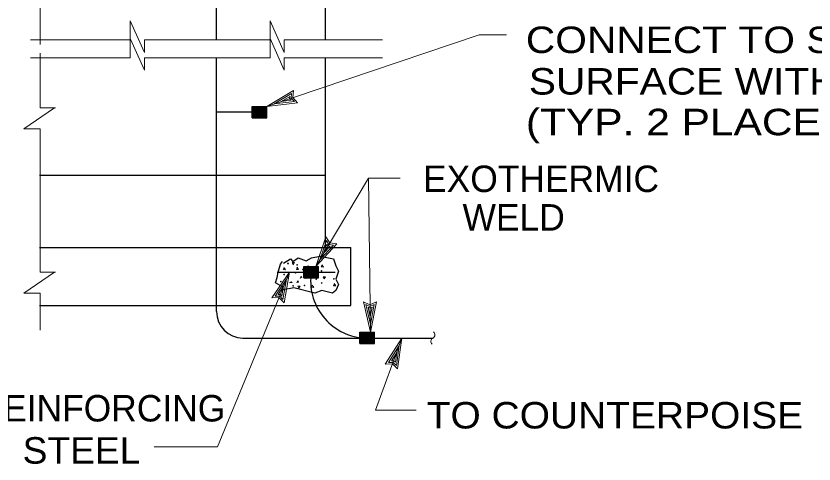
# Model space of a CAD drawing. Extents: x -39.6 to 16.1, y -17.6 to 34.
# Drawn here: x -5.055 to -1.286, y 5.207 to 7.321 of the extents above; entities that cross this region are included whole.
import ezdxf
from ezdxf.enums import TextEntityAlignment as Align

# ---------------------------------------------------------------- set-up
doc = ezdxf.new("R2010")
doc.units = 0
doc.header["$LTSCALE"] = 0.05
doc.layers.add('1', color=7, linetype='Continuous', lineweight=13)
doc.layers.add('2', color=7, linetype='Continuous', lineweight=13)

msp = doc.modelspace()

# ---------------------------------------------------------------- linework, layer by layer
at = {"layer": '1', "lineweight": 25}
for p, q in [((-4.10821, 7.20742), (-4.10821, 8.14042)), ((-3.59321, 7.20842), (-3.59321, 7.50542)), ((-4.10821, 5.92642), (-4.10821, 7.12442)), ((-3.59321, 6.22942), (-3.59321, 7.12442)), ((-4.10821, 6.86942), (-3.94021, 6.86942)), ((-3.94021, 6.84142), (-3.94021, 6.89442)), ((-3.94021, 6.89442), (-3.87121, 6.89442)), ((-3.94021, 6.89342), (-3.87121, 6.89342)), ((-3.94021, 6.89242), (-3.87121, 6.89242)), ((-3.94021, 6.89142), (-3.87121, 6.89142)), ((-3.94021, 6.89042), (-3.87121, 6.89042)), ((-3.94021, 6.88942), (-3.87121, 6.88942)), ((-3.94021, 6.88842), (-3.87121, 6.88842)), ((-3.94021, 6.88742), (-3.87121, 6.88742)), ((-3.94021, 6.88642), (-3.87121, 6.88642)), ((-3.94021, 6.88542), (-3.87121, 6.88542)), ((-3.94021, 6.88442), (-3.87121, 6.88442)), ((-3.94021, 6.88342), (-3.87121, 6.88342)), ((-3.94021, 6.88242), (-3.87121, 6.88242)), ((-3.94021, 6.88142), (-3.87121, 6.88142)), ((-3.94021, 6.88042), (-3.87121, 6.88042)), ((-3.94021, 6.87942), (-3.87121, 6.87942)), ((-3.94021, 6.87842), (-3.87121, 6.87842)), ((-3.94021, 6.87742), (-3.87121, 6.87742)), ((-3.94021, 6.87642), (-3.87121, 6.87642)), ((-3.94021, 6.87542), (-3.87121, 6.87542)), ((-3.94021, 6.87442), (-3.87121, 6.87442)), ((-3.94021, 6.87342), (-3.87121, 6.87342)), ((-3.94021, 6.87242), (-3.87121, 6.87242)), ((-3.94021, 6.87142), (-3.87121, 6.87142)), ((-3.94021, 6.87042), (-3.87121, 6.87042)), ((-3.94021, 6.86942), (-3.87121, 6.86942)), ((-3.94021, 6.86842), (-3.87121, 6.86842)), ((-3.94021, 6.86742), (-3.87121, 6.86742)), ((-3.94021, 6.86642), (-3.87121, 6.86642)), ((-3.94021, 6.86542), (-3.87121, 6.86542)), ((-3.94021, 6.86442), (-3.87121, 6.86442)), ((-3.94021, 6.86342), (-3.87121, 6.86342)), ((-3.94021, 6.86242), (-3.87121, 6.86242)), ((-3.94021, 6.86142), (-3.87121, 6.86142)), ((-3.94021, 6.86042), (-3.87121, 6.86042)), ((-3.87121, 6.84142), (-3.87121, 6.89442)), ((-3.94021, 6.85942), (-3.87121, 6.85942)), ((-3.94021, 6.85842), (-3.87121, 6.85842)), ((-3.94021, 6.85742), (-3.87121, 6.85742)), ((-3.94021, 6.85642), (-3.87121, 6.85642)), ((-3.94021, 6.85542), (-3.87121, 6.85542)), ((-3.94021, 6.85442), (-3.87121, 6.85442)), ((-3.94021, 6.85342), (-3.87121, 6.85342)), ((-3.94021, 6.85242), (-3.87121, 6.85242)), ((-3.94021, 6.85142), (-3.87121, 6.85142)), ((-3.94021, 6.85042), (-3.87121, 6.85042)), ((-3.94021, 6.84942), (-3.87121, 6.84942)), ((-3.94021, 6.84842), (-3.87121, 6.84842)), ((-3.94021, 6.84742), (-3.87121, 6.84742)), ((-3.94021, 6.84642), (-3.87121, 6.84642)), ((-3.94021, 6.84542), (-3.87121, 6.84542)), ((-3.94021, 6.84442), (-3.87121, 6.84442)), ((-3.94021, 6.84342), (-3.87121, 6.84342)), ((-3.94021, 6.84242), (-3.87121, 6.84242)), ((-3.94021, 6.84142), (-3.87121, 6.84142)), ((-4.94421, 6.57042), (-3.59321, 6.57042)), ((-4.94421, 6.22942), (-3.47421, 6.22942)), ((-3.47421, 5.95542), (-3.47421, 6.22942)), ((-3.82121, 6.11242), (-3.54821, 6.11242)), ((-3.69521, 6.08542), (-3.69521, 6.13842)), ((-3.69521, 6.13842), (-3.62621, 6.13842)), ((-3.69521, 6.13742), (-3.62621, 6.13742)), ((-3.69521, 6.13642), (-3.62621, 6.13642)), ((-3.69521, 6.13542), (-3.62621, 6.13542)), ((-3.69521, 6.13442), (-3.62621, 6.13442)), ((-3.69521, 6.13342), (-3.62621, 6.13342)), ((-3.69521, 6.13242), (-3.62621, 6.13242)), ((-3.69521, 6.13142), (-3.62621, 6.13142)), ((-3.69521, 6.13042), (-3.62621, 6.13042)), ((-3.69521, 6.12942), (-3.62621, 6.12942)), ((-3.69521, 6.12842), (-3.62621, 6.12842)), ((-3.69521, 6.12742), (-3.62621, 6.12742)), ((-3.69521, 6.12642), (-3.62621, 6.12642)), ((-3.69521, 6.12542), (-3.62621, 6.12542)), ((-3.69521, 6.12442), (-3.62621, 6.12442)), ((-3.69521, 6.12342), (-3.62621, 6.12342)), ((-3.69521, 6.12242), (-3.62621, 6.12242)), ((-3.69521, 6.12142), (-3.62621, 6.12142)), ((-3.69521, 6.12042), (-3.62621, 6.12042)), ((-3.69521, 6.11942), (-3.62621, 6.11942)), ((-3.69521, 6.11842), (-3.62621, 6.11842)), ((-3.69521, 6.11742), (-3.62621, 6.11742)), ((-3.69521, 6.11642), (-3.62621, 6.11642)), ((-3.69521, 6.11542), (-3.62621, 6.11542)), ((-3.69521, 6.11442), (-3.62621, 6.11442)), ((-3.69521, 6.11342), (-3.62621, 6.11342)), ((-3.69521, 6.11242), (-3.62621, 6.11242)), ((-3.69521, 6.11142), (-3.62621, 6.11142)), ((-3.69521, 6.11042), (-3.62621, 6.11042)), ((-3.69521, 6.10942), (-3.62621, 6.10942)), ((-3.69521, 6.10842), (-3.62621, 6.10842)), ((-3.69521, 6.10742), (-3.62621, 6.10742)), ((-3.69521, 6.10642), (-3.62621, 6.10642)), ((-3.62621, 6.08542), (-3.62621, 6.13842)), ((-3.69521, 6.10542), (-3.62621, 6.10542)), ((-3.69521, 6.10442), (-3.62621, 6.10442)), ((-3.69521, 6.10342), (-3.62621, 6.10342)), ((-3.69521, 6.10242), (-3.62621, 6.10242)), ((-3.69521, 6.10142), (-3.62621, 6.10142)), ((-3.69521, 6.10042), (-3.62621, 6.10042)), ((-3.69521, 6.09942), (-3.62621, 6.09942)), ((-3.69521, 6.09842), (-3.62621, 6.09842)), ((-3.69521, 6.09742), (-3.62621, 6.09742)), ((-3.69521, 6.09642), (-3.62621, 6.09642)), ((-3.69521, 6.09542), (-3.62621, 6.09542)), ((-3.69521, 6.09442), (-3.62621, 6.09442)), ((-3.69521, 6.09342), (-3.62621, 6.09342)), ((-3.69521, 6.09242), (-3.62621, 6.09242)), ((-3.69521, 6.09142), (-3.62621, 6.09142)), ((-3.69521, 6.09042), (-3.62621, 6.09042)), ((-3.69521, 6.08942), (-3.62621, 6.08942)), ((-3.69521, 6.08842), (-3.62621, 6.08842)), ((-3.69521, 6.08742), (-3.62621, 6.08742)), ((-3.69521, 6.08642), (-3.62621, 6.08642)), ((-3.69521, 6.08542), (-3.62621, 6.08542)), ((-4.94421, 5.95542), (-3.47421, 5.95542)), ((-3.43121, 5.77542), (-3.43121, 5.82842)), ((-3.43121, 5.82842), (-3.36221, 5.82842)), ((-3.43121, 5.82742), (-3.36221, 5.82742)), ((-3.43121, 5.82642), (-3.36221, 5.82642)), ((-3.43121, 5.82542), (-3.36221, 5.82542)), ((-3.43121, 5.82442), (-3.36221, 5.82442)), ((-3.43121, 5.82342), (-3.36221, 5.82342)), ((-3.43121, 5.82242), (-3.36221, 5.82242)), ((-3.43121, 5.82142), (-3.36221, 5.82142)), ((-3.43121, 5.82042), (-3.36221, 5.82042)), ((-3.43121, 5.81942), (-3.36221, 5.81942)), ((-3.43121, 5.81842), (-3.36221, 5.81842)), ((-3.43121, 5.81742), (-3.36221, 5.81742)), ((-3.43121, 5.81642), (-3.36221, 5.81642)), ((-3.43121, 5.81542), (-3.36221, 5.81542)), ((-3.43121, 5.81442), (-3.36221, 5.81442)), ((-3.43121, 5.81342), (-3.36221, 5.81342)), ((-3.43121, 5.81242), (-3.36221, 5.81242)), ((-3.43121, 5.81142), (-3.36221, 5.81142)), ((-3.43121, 5.81042), (-3.36221, 5.81042)), ((-3.43121, 5.80942), (-3.36221, 5.80942)), ((-3.43121, 5.80842), (-3.36221, 5.80842)), ((-3.43121, 5.80742), (-3.36221, 5.80742)), ((-3.43121, 5.80642), (-3.36221, 5.80642)), ((-3.43121, 5.80542), (-3.36221, 5.80542)), ((-3.43121, 5.80442), (-3.36221, 5.80442)), ((-3.36221, 5.77542), (-3.36221, 5.82842)), ((-3.98321, 5.80142), (-3.08721, 5.80142)), ((-3.43121, 5.80342), (-3.36221, 5.80342)), ((-3.43121, 5.80242), (-3.36221, 5.80242)), ((-3.43121, 5.80142), (-3.36221, 5.80142)), ((-3.43121, 5.80042), (-3.36221, 5.80042)), ((-3.43121, 5.79942), (-3.36221, 5.79942)), ((-3.43121, 5.79842), (-3.36221, 5.79842)), ((-3.43121, 5.79742), (-3.36221, 5.79742)), ((-3.43121, 5.79642), (-3.36221, 5.79642)), ((-3.43121, 5.79542), (-3.36221, 5.79542)), ((-3.43121, 5.79442), (-3.36221, 5.79442)), ((-3.43121, 5.79342), (-3.36221, 5.79342)), ((-3.43121, 5.79242), (-3.36221, 5.79242)), ((-3.43121, 5.79142), (-3.36221, 5.79142)), ((-3.43121, 5.79042), (-3.36221, 5.79042)), ((-3.43121, 5.78942), (-3.36221, 5.78942)), ((-3.43121, 5.78842), (-3.36221, 5.78842)), ((-3.43121, 5.78742), (-3.36221, 5.78742)), ((-3.43121, 5.78642), (-3.36221, 5.78642)), ((-3.43121, 5.78542), (-3.36221, 5.78542)), ((-3.43121, 5.78442), (-3.36221, 5.78442)), ((-3.43121, 5.78342), (-3.36221, 5.78342)), ((-3.43121, 5.78242), (-3.36221, 5.78242)), ((-3.43121, 5.78142), (-3.36221, 5.78142)), ((-3.43121, 5.78042), (-3.36221, 5.78042)), ((-3.43121, 5.77942), (-3.36221, 5.77942)), ((-3.43121, 5.77842), (-3.36221, 5.77842)), ((-3.43121, 5.77742), (-3.36221, 5.77742)), ((-3.43121, 5.77642), (-3.36221, 5.77642)), ((-3.43121, 5.77542), (-3.36221, 5.77542))]:
    msp.add_line(p, q, dxfattribs=at)
at = {"layer": '1'}
for p, q in [((-4.94121, 7.18642), (-4.94121, 7.42342)), ((-4.51521, 7.20842), (-4.51521, 7.29842)), ((-4.51521, 7.29842), (-4.44821, 7.14942)), ((-3.85521, 7.20842), (-3.85521, 7.29842)), ((-3.85521, 7.29842), (-3.78821, 7.14942)), ((-4.98721, 7.20842), (-4.51521, 7.20842)), ((-4.51521, 7.12442), (-4.51521, 7.21442)), ((-4.51521, 7.21442), (-4.44821, 7.06542)), ((-4.44821, 7.14942), (-4.44821, 7.20842)), ((-4.44821, 7.20842), (-3.85521, 7.20842)), ((-3.85521, 7.12442), (-3.85521, 7.21442)), ((-3.85521, 7.21442), (-3.78821, 7.06542)), ((-3.78821, 7.14942), (-3.78821, 7.20842)), ((-3.78821, 7.20842), (-3.32421, 7.20842)), ((-2.86821, 7.23242), (-2.73821, 7.23242)), ((-4.98721, 7.12442), (-4.51521, 7.12442)), ((-4.94121, 6.88842), (-4.94121, 7.14542)), ((-4.44821, 7.06542), (-4.44821, 7.12442)), ((-4.44821, 7.12442), (-3.85521, 7.12442)), ((-3.78821, 7.06542), (-3.78821, 7.12442)), ((-3.78821, 7.12442), (-3.32421, 7.12442)), ((-3.83621, 6.90642), (-3.75321, 6.95542)), ((-3.80221, 6.91742), (-3.76221, 6.94142)), ((-3.76221, 6.94142), (-3.76321, 6.93042)), ((-3.75321, 6.95542), (-3.75521, 6.93342)), ((-3.87121, 6.89442), (-3.72521, 6.91142)), ((-3.83621, 6.90642), (-3.74021, 6.91742)), ((-3.80221, 6.91742), (-3.75621, 6.92342)), ((-3.76321, 6.93042), (-3.75621, 6.92342)), ((-3.75521, 6.93342), (-3.74021, 6.91742)), ((-5.01821, 6.78842), (-4.87321, 6.88842)), ((-4.94121, 6.88842), (-4.86921, 6.88842)), ((-5.01821, 6.78842), (-4.94121, 6.78842)), ((-4.94121, 6.11242), (-4.94121, 6.78842)), ((-3.39021, 6.55642), (-3.63921, 6.13842)), ((-3.39021, 6.55642), (-3.24021, 6.55642)), ((-3.39021, 6.55642), (-3.38121, 5.82842)), ((-3.63921, 6.13842), (-3.59221, 6.27842)), ((-3.62021, 6.17042), (-3.58921, 6.26142)), ((-3.58921, 6.26142), (-3.57721, 6.24342)), ((-3.63921, 6.13842), (-3.53921, 6.24642)), ((-3.62021, 6.17042), (-3.55521, 6.24042)), ((-3.60221, 6.20142), (-3.58721, 6.24442)), ((-3.60221, 6.20142), (-3.57121, 6.23542)), ((-3.58721, 6.24442), (-3.58121, 6.23642)), ((-3.58121, 6.23642), (-3.57121, 6.23542)), ((-3.57721, 6.24342), (-3.55521, 6.24042)), ((-5.01821, 6.01242), (-4.87321, 6.11242)), ((-4.94121, 6.11242), (-4.86921, 6.11242)), ((-3.76321, 6.11242), (-3.84721, 5.99142)), ((-3.76321, 6.11242), (-3.78921, 5.96742)), ((-3.77721, 6.07842), (-3.83121, 5.99942)), ((-3.77721, 6.07842), (-3.79421, 5.98342)), ((-3.79121, 6.04542), (-3.81621, 6.00642)), ((-3.79121, 6.04542), (-3.79921, 5.99942)), ((-5.01821, 6.01242), (-4.94121, 6.01242)), ((-4.94121, 5.83842), (-4.94121, 6.01242)), ((-3.80921, 5.99942), (-3.83121, 5.99942)), ((-3.80621, 6.00742), (-3.81621, 6.00642)), ((-3.79421, 5.98342), (-3.80921, 5.99942)), ((-3.79921, 5.99942), (-3.80621, 6.00742)), ((-3.38121, 5.82842), (-3.41421, 5.97242)), ((-3.38121, 5.86542), (-3.40321, 5.95942)), ((-3.40321, 5.95942), (-3.38321, 5.95042)), ((-3.38321, 5.95042), (-3.36321, 5.95942)), ((-3.38121, 5.82842), (-3.35221, 5.97242)), ((-3.38121, 5.86542), (-3.36321, 5.95942)), ((-3.38221, 5.90142), (-3.39221, 5.94642)), ((-3.39221, 5.94642), (-3.38221, 5.94242)), ((-3.38221, 5.90142), (-3.37321, 5.94642)), ((-3.38221, 5.94242), (-3.37321, 5.94642)), ((-3.35721, 5.46142), (-3.23221, 5.80142)), ((-3.23221, 5.80142), (-3.31121, 5.67742)), ((-3.23221, 5.80142), (-3.25321, 5.65542)), ((-3.24521, 5.76642), (-3.29621, 5.68542)), ((-3.25721, 5.73242), (-3.28121, 5.69342)), ((-3.25721, 5.73242), (-3.26321, 5.68742)), ((-3.24521, 5.76642), (-3.25821, 5.67142)), ((-3.27121, 5.69442), (-3.28121, 5.69342)), ((-3.26321, 5.68742), (-3.27121, 5.69442)), ((-3.27421, 5.68642), (-3.29621, 5.68542)), ((-3.25821, 5.67142), (-3.27421, 5.68642)), ((-3.35721, 5.46142), (-3.16521, 5.46142))]:
    msp.add_line(p, q, dxfattribs=at)
for points in [[(-2.86821, 7.23242), (-3.87121, 6.89442), (-3.74421, 6.96942)], [(-3.74421, 6.96942), (-3.74821, 6.93642), (-3.72521, 6.91142)], [(-3.59221, 6.27842), (-3.57221, 6.25042), (-3.53921, 6.24642)], [(-4.40221, 5.28742), (-4.10321, 5.28742), (-3.76321, 6.11242)], [(-3.78921, 5.96742), (-3.81321, 5.99242), (-3.84721, 5.99142)], [(-3.41421, 5.97242), (-3.38321, 5.95842), (-3.35221, 5.97242)], [(-3.25321, 5.65542), (-3.27721, 5.67942), (-3.31121, 5.67742)]]:
    msp.add_lwpolyline(points, dxfattribs=at)
at = {"layer": '1', "lineweight": 25}
msp.add_lwpolyline([(-3.79221, 6.15442), (-3.75921, 6.17442), (-3.74721, 6.16242), (-3.72221, 6.17942), (-3.70921, 6.17442), (-3.68521, 6.16642), (-3.66021, 6.17942), (-3.61821, 6.18742), (-3.55621, 6.17442), (-3.54421, 6.14142), (-3.53121, 6.11642), (-3.54421, 6.07942), (-3.53121, 6.05442), (-3.54421, 6.02542), (-3.56021, 6.01342), (-3.61021, 6.02542), (-3.64321, 6.01342), (-3.74321, 6.03842), (-3.79221, 6.02942), (-3.79721, 6.04242), (-3.83021, 6.06242), (-3.82121, 6.08742), (-3.81721, 6.11242), (-3.80521, 6.14942), (-3.79721, 6.16242)], dxfattribs=at)
for centre, radius, start, end in [((-3.39332, 6.07059), 0.27014, 171.09245, 265.14059), ((-3.98321, 5.92642), 0.125, 180, 270)]:
    msp.add_arc(centre, radius, start, end, dxfattribs=at)
at = {"layer": '1'}
for centre, start, end in [((-3.09508, 5.81667), 302.92471, 49.18492), ((-3.07733, 5.78617), 122.92471, 229.18492)]:
    msp.add_arc(centre, 0.01817, start, end, dxfattribs=at)
at = {"layer": '2'}
msp.add_line((-3.68121, 6.13742), (-3.67421, 6.14242), dxfattribs=at)
for points in [[(-3.74621, 6.14942), (-3.75121, 6.15842), (-3.74021, 6.15842), (-3.74621, 6.14742)], [(-3.60821, 6.14742), (-3.61321, 6.13742), (-3.60221, 6.13642), (-3.61021, 6.14742)], [(-3.78821, 6.13442), (-3.79321, 6.12442), (-3.78221, 6.12342), (-3.79021, 6.13442)], [(-3.72521, 6.13542), (-3.73021, 6.12542), (-3.72021, 6.12442), (-3.72821, 6.13542)], [(-3.67421, 6.14242), (-3.67321, 6.13542), (-3.68121, 6.13542)], [(-3.66821, 6.08942), (-3.66421, 6.09342), (-3.66021, 6.08942), (-3.66721, 6.08842)], [(-3.64721, 6.10242), (-3.64221, 6.10442), (-3.64021, 6.09942), (-3.64721, 6.10142)], [(-3.59921, 6.08242), (-3.60421, 6.09042), (-3.59321, 6.09042), (-3.59921, 6.08042)], [(-3.76121, 6.06342), (-3.75621, 6.06642), (-3.75121, 6.06342), (-3.76321, 6.06142)], [(-3.71921, 6.03742), (-3.72421, 6.04642), (-3.71321, 6.04642), (-3.71921, 6.03642)], [(-3.65421, 6.05142), (-3.65921, 6.04142), (-3.64921, 6.04042), (-3.65621, 6.05142)], [(-3.55021, 6.05842), (-3.55521, 6.04842), (-3.54521, 6.04742), (-3.55321, 6.05842)]]:
    msp.add_lwpolyline(points, dxfattribs=at)
for points in [[(-3.72821, 6.06342), (-3.72321, 6.07142), (-3.72021, 6.06542)], [(-3.71321, 6.08442), (-3.70821, 6.09342), (-3.70521, 6.08742)]]:
    msp.add_lwpolyline(points, close=True, dxfattribs=at)
for centre in [(-3.77046, 6.15329), (-3.72771, 6.14654), (-3.73521, 6.10954), (-3.69996, 6.12479), (-3.65371, 6.12379), (-3.61246, 6.11804), (-3.80421, 6.06754), (-3.78896, 6.10129), (-3.76971, 6.08604), (-3.68471, 6.08429), (-3.63671, 6.07854), (-3.55421, 6.08029), (-3.74621, 6.04729), (-3.69221, 6.04979), (-3.61146, 6.06079)]:
    msp.add_circle(centre, 0.00162, dxfattribs=at)

# ---------------------------------------------------------------- texts
at = {"layer": '1'}
for s, width, p in [('CONNECT TO STEEL ARCH EXTERIOR', 1.15, (-2.64721, 7.14642)), ('SURFACE WITH EXOTHERMIC WELD', 1.15, (-2.63321, 6.95042)), ('(TYP. 2 PLACES)', 1.2, (-2.64721, 6.75842))]:
    msp.add_text(s, height=0.125, dxfattribs=dict(at, width=width)).set_placement(p)
for s, p in [('EXOTHERMIC', (-2.01821, 6.49042)), ('WELD', (-2.46321, 6.30842))]:
    msp.add_text(s, height=0.125, dxfattribs=at).set_placement(p, align=Align.RIGHT)
msp.add_text('REINFORCING', height=0.125, dxfattribs=at).set_placement((-4.65171, 5.40742), align=Align.CENTER)
for s, width, p in [('TO COUNTERPOISE', 1.1, (-2.22671, 5.37442)), ('STEEL', 1.05, (-4.74571, 5.20842))]:
    msp.add_text(s, height=0.125, dxfattribs=dict(at, width=width)).set_placement(p, align=Align.CENTER)

doc.saveas('drawing.dxf')
